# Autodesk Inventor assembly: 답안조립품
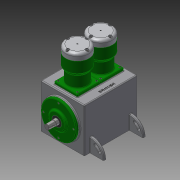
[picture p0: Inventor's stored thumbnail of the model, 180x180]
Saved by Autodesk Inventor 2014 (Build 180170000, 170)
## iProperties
Created: 2017-03
Part Number: 답안조립품
Document SubType Name: Assembly
Designer: SEC
Author: SEC
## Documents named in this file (18)
- C:\Documents and Settings\SEC\바탕 화면\370307V1005\답안조립품.iam
- C:\Documents and Settings\SEC\바탕 화면\370307V1005\본체.ipt
- C:\Documents and Settings\SEC\바탕 화면\370307V1005\너트 M4.ipt
- C:\Documents and Settings\SEC\바탕 화면\370307V1005\베어링 20 x 47 x 14.ipt
- C:\Documents and Settings\SEC\바탕 화면\370307V1005\볼트 M4 x 8.ipt
- C:\Documents and Settings\SEC\바탕 화면\370307V1005\볼트 M5 x 20.ipt
- C:\Documents and Settings\SEC\바탕 화면\370307V1005\실린더.ipt
- C:\Documents and Settings\SEC\바탕 화면\370307V1005\실린더헤드.ipt
- C:\Documents and Settings\SEC\바탕 화면\370307V1005\앞커버.ipt
- C:\Documents and Settings\SEC\바탕 화면\370307V1005\오일 실 20 35 8.ipt
- C:\Documents and Settings\SEC\바탕 화면\370307V1005\육각머리볼트 M4 x 16.ipt
- C:\Documents and Settings\SEC\바탕 화면\370307V1005\커넥팅로드.ipt
- C:\Documents and Settings\SEC\바탕 화면\370307V1005\커넥팅로드 엔드.ipt
- C:\Documents and Settings\SEC\바탕 화면\370307V1005\크랭크축.ipt
- C:\Documents and Settings\SEC\바탕 화면\370307V1005\피스톤.ipt
- C:\Documents and Settings\SEC\바탕 화면\370307V1005\피스톤핀.ipt
- C:\Documents and Settings\SEC\바탕 화면\370307V1005\가변스프링2.ipt
- C:\Documents and Settings\SEC\바탕 화면\370307V1005\가변스프링1.ipt
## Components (34 placed, 8 different names)
1. KS B 1002 A+B - 미터 A + B M4 x 16:1
2. KS B 1012 스타일 1 - 미터 A M4:1
3. KS B 1002 A+B - 미터 A + B M4 x 16:3
4. KS B 1012 스타일 1 - 미터 A M4:3
5. 피스톤:1
6. 피스톤핀:1
7. 피스톤:2
8. 피스톤핀:2
9. KS B 1002 A+B - 미터 A + B M4 x 16:2
10. KS B 1012 스타일 1 - 미터 A M4:2
11. KS B 1002 A+B - 미터 A + B M4 x 16:4
12. KS B 1012 스타일 1 - 미터 A M4:4
13. 가변스프링1:1
14. 가변스프링2:1
15. ISO 4762 M4 x 8:1
16. ISO 4762 M4 x 8:3
17. ISO 4762 M4 x 8:4
18. ISO 4762 M4 x 8:5
19. ISO 4762 M4 x 8:2
20. ISO 4762 M4 x 8:6
21. ISO 4762 M4 x 8:7
22. ISO 4762 M4 x 8:8
23. ISO 4762 M4 x 8:9
24. ISO 4762 M4 x 8:10
25. ISO 4762 M4 x 8:11
26. ISO 4762 M4 x 8:12
27. ISO 4762 M5 x 20:1
28. ISO 4762 M5 x 20:3
29. ISO 4762 M5 x 20:4
30. ISO 4762 M5 x 20:5
31. ISO 4762 M5 x 20:2
32. ISO 4762 M5 x 20:6
33. ISO 4762 M5 x 20:7
34. ISO 4762 M5 x 20:8
